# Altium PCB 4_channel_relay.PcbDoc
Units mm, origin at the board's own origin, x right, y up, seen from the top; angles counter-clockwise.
Board outline 102.27 x 70.58 mm, 2 copper layers (Top Layer, Bottom Layer); 40 components, 52 nets, 202 pads, 42 vias.
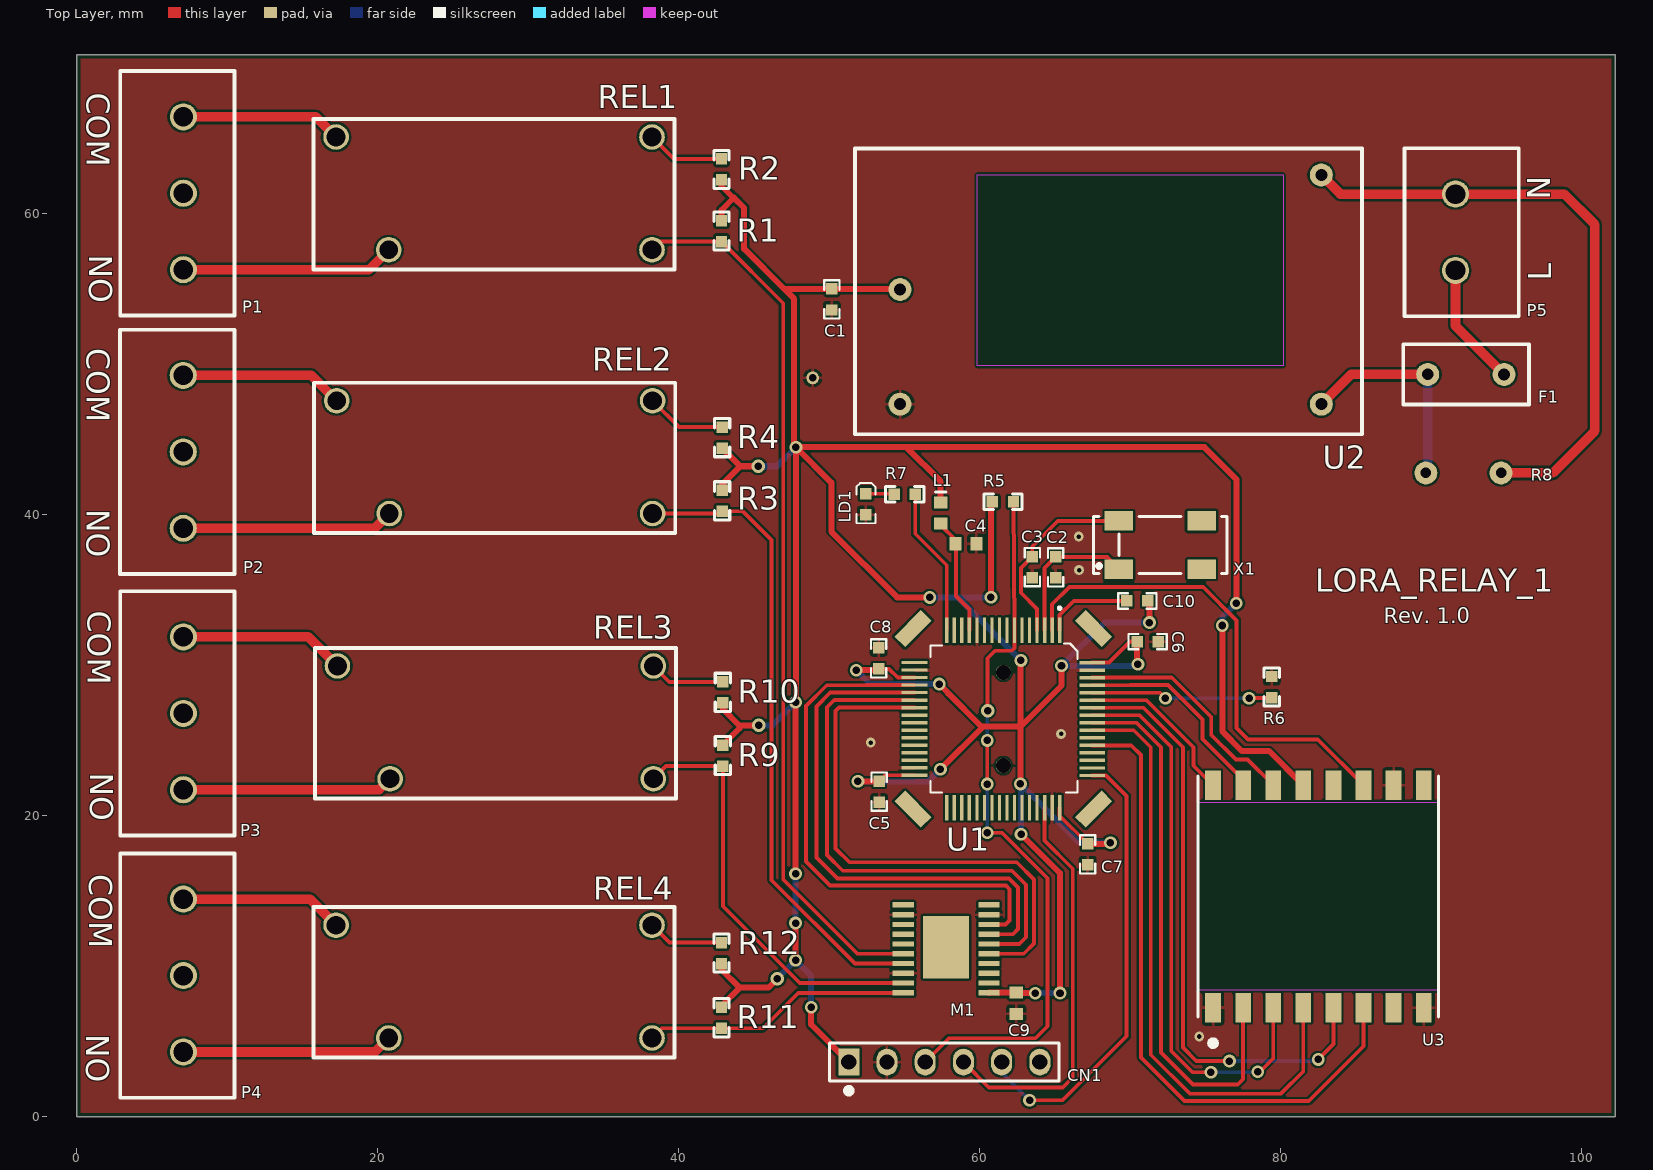
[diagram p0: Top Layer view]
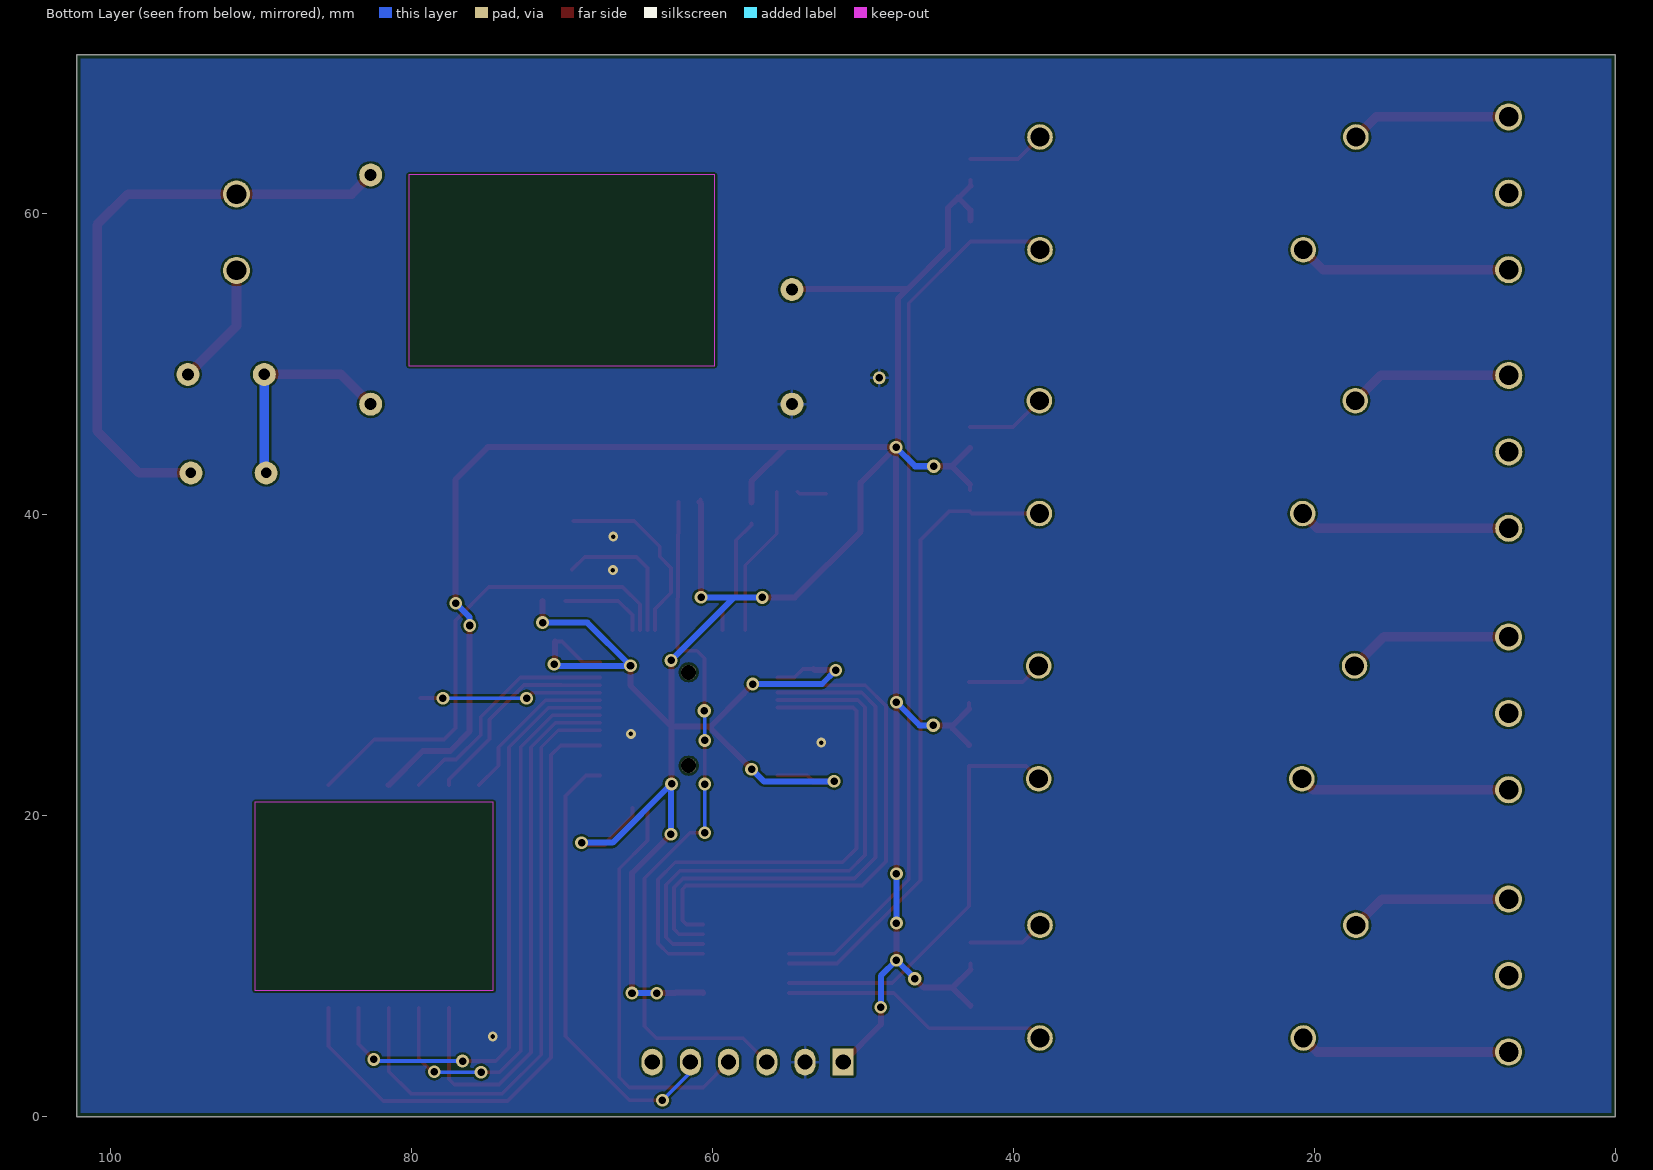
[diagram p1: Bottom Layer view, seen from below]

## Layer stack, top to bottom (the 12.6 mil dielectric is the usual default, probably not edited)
Top Solder: solder mask 0.0102, Solder Resist, Dk 3.5
Top Layer: signal copper 0.0356
Dielectric 1: dielectric 0.32, FR-4, Dk 4.8
Bottom Layer: signal copper 0.0356
Bottom Solder: solder mask 0.0102, Solder Resist, Dk 3.5

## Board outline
0,-0.01 102.27,-0.01 102.27,70.57 0,70.57

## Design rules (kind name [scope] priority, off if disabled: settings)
BoardOutlineClearance [All] p1: gap=0.25 ignorepadtopadclearanceinfootprint=FALSE except(0: Arc-SplitContinuation Track-SplitContinuation SMDPad-SplitContinuation THPad-SplitContinuation Via-SplitContinuation Fill-SplitContinuation Poly-SplitContinuation Region-SplitContinuation Text-SplitContinuation)
Clearance [InNetClass('240VAC')] p1: gap=0.15 ignorepadtopadclearanceinfootprint=FALSE except(0: Arc-Hole Track-Hole SMDPad-Hole THPad-Hole Via-Hole Fill-Hole Poly-Hole Region-Hole Text-Hole; 3: Arc-Arc Arc-Track Track-Track)
Clearance Clearance-xPP-xTP-xTT [All] p2: gap=0.15 ignorepadtopadclearanceinfootprint=FALSE except(0: Arc-Hole Track-Hole SMDPad-Hole THPad-Hole Via-Hole Fill-Hole Poly-Hole Region-Hole Text-Hole)
ComponentClearance [All] p1: gap=0.25 collisioncheckmode=3 verticalgap=0.25 showdistances=FALSE
DiffPairsRouting [All] p1: maxlimit=0.25 minlimit=0.25 mostfreqgap=0.25 toplayer_minwidth=0.381 toplayer_maxwidth=0.381 toplayer_prefwidth=0.381 bottomlayer_minwidth=0.381 bottomlayer_maxwidth=0.381 bottomlayer_prefwidth=0.381 maxuncoupledlength=12.5
Height [All] p1: minheight=0 maxheight=25 prefheight=12.5
HoleSize HoleSize-PTH [All] p1: absolutevalues=TRUE maxlimit=2 minlimit=0.3 maxpercent=80.000 minpercent=20.000
HoleToHoleClearance [All] p1: gap=0.35 allowstackedmicrovias=TRUE
MinimumAnnularRing "Minimum IAR  >0.45mm" [((ObjectKind = 'Pad') OR (ObjectKind = 'Via')) And (Layer = 'MultiLayer') And (HoleDiameter > AsMM(0.45))] p1: minimumring=0.125 // minimum inner annular ring for pads > 0.45mm finished hole size
MinimumAnnularRing "Minimum IAR <=0.45mm" [((ObjectKind = 'Pad') OR (ObjectKind = 'Via')) And (Layer = 'MultiLayer') And (HoleDiameter <= AsMM(0.45))] p2: minimumring=0.175 // minimum inner annular ring for pads <= 0.45mm finished hole size
MinimumSolderMaskSliver [All] p1: minsoldermaskwidth=0.08
PlaneClearance PlaneClearance-IPI [All] p1: clearance=0.25
PlaneConnect [All] p1: planeconnectstyle=Relief reliefexpansion=0.175 reliefentries=4 reliefconductorwidth=0.2 reliefairgap=0.2
PolygonConnect PolygonConnect-xTW [All] p1: connectstyle=Relief reliefconductorwidth=0.2 reliefentries=4 polygonreliefangle="90 Angle" airgapwidth=0.2
RoutingCorners [All] p1: cornerstyle=45-Degree minsetback=2.5 maxsetback=2.5
RoutingVias "RoutingVias > 0.45mm" [(ObjectKind = 'Via') And (HoleDiameter > AsMM(0.45))] p1: holewidth=0.5 width=0.85 viastyle="Through Hole" minholewidth=0.5 minwidth=0.85 maxholewidth=0.9 maxwidth=1.25 // finishet hole size > 0.45mm
RoutingVias "RoutingVias <= 0.45mm" [(ObjectKind = 'Via') And (HoleDiameter <= AsMM(0.45))] p2: holewidth=0.3 width=0.65 viastyle="Through Hole" minholewidth=0.25 minwidth=0.6 maxholewidth=0.45 maxwidth=0.8 // finishet hole size <= 0.45mm
SilkToSilkClearance [All] p1: silktosilkclearance=0.2
SilkToSolderMaskClearance SilkscreenOverComponentPads [IsPad] p1: minsilkscreentomaskgap=0.01 clearancetoexposedcopper=TRUE
SolderMaskExpansion [All] p1: expansion=0
UnRoutedNet [All] p1: checkbadconnections=TRUE
Width Width-xTW [All] p1: maxlimit=1.5 minlimit=0.15 preferedwidth=0.2
18 further rules are at their usual default settings.

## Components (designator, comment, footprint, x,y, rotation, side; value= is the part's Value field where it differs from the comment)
C1 "100nF" 0603C 50.2,54.3 r90 top value=0.1µF
C2 "10pF[N/A]" 0603C 65.07,36.49 r90 top value=10pF
C3 "10pF[N/A]" 0603C 63.52,36.51 r90 top
C4 "Cap Semi" 1608[0603] 59.1,38.07 r0 top
C5 "100nF" 0603C 53.335,21.591 r90 top
C6 "100nF" 0603C 71.19,31.56 r180 top
C7 "100nF" 0603C 67.2,17.42 r90 top
C8 "100nF" 0603C 53.3,30.445 r270 top
C9 "Cap Semi" 1608[0603] 62.45,7.52 r270 top
C10 "100nF" 0603C 70.5,34.26 r0 top value=0.1µF
CN1 "Header 6X1" 1*6P 51.32,3.61 r0 top
F1 "fuse" fuse 94.88,49.32 r180 top value="1A 250VAC"
L1 "Bead" INDC1608L 57.424,40.099 r270 top value="600 OHM"
LD1 "Green" 0603D 52.457,40.695 r90 top value=571nm
M1 "MAX4821" MAX4821 60.64,8.21 r180 top
P1 "relay_header_3" ac_header_3 2.89,53.24 r90 top
P2 "relay_header_3" ac_header_3 2.88,36.05 r90 top
P3 "relay_header_3" ac_header_3 2.89,18.67 r90 top
P4 "relay_header_3" ac_header_3 2.89,1.24 r90 top
P5 "AC_HEADER" ac_header_2 95.85,64.35 r270 top
R1 "50" 0603R 42.86,58.845 r90 top value="50 Ohms"
R2 "50" 0603R 42.86,62.945 r270 top
R3 "50" 0603R 42.9,40.916 r90 top
R4 "50" 0603R 42.9,45.115 r270 top
R5 "4K7" 0603R 61.57,40.85 r0 top value="4.7 kOhms"
R6 "4K7" 0603R 79.44,28.54 r90 top
R7 "510" 0603R 55.04,41.351 r0 top value="510 Ohms"
R8 "" varistor 94.68,42.77 r180 top value="360V 400A"
R9 "50" 0603R 42.95,23.985 r90 top
R10 "50" 0603R 42.95,28.185 r270 top
R11 "50" 0603R 42.86,6.555 r90 top
R12 "50" 0603R 42.86,10.855 r270 top
REL1 "ADW1103W" ADW1103W 39.74,37.7 r180 top
REL2 "ADW1103W" ADW1103W 39.78,20.17 r180 top
REL3 "ADW1103W" ADW1103W 39.83,2.54 r180 top
REL4 "ADW1103W" ADW1103W 39.74,-14.69 r180 top
U1 "MCU_LQFP64" LQFP64 61.59,26.417 r180 top
U2 "RAC01-3.3SC" RAC01-3.3SC 82.73,47.34 r180 top
U3 "RFM95W-868S2" XCVR_RFM95W-868S2 82.534,14.618 r90 top
X1 "32.768K[N/A]" XTAL_4SM_8X3R8 72.02,37.98 r0 top

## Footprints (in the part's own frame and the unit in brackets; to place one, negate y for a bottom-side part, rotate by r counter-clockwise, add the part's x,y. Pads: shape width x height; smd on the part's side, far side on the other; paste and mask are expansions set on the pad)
1*6P [mil]
  rect 55x70 hole 40: 1(0,0)
  oval 55x70 hole 40: 2(400,0) 3(100,0) 4(300,0) 5(200,0) 6(500,0)
  silkscreen extent -50,-82 550,50
0603C [mil]
  rect 30x30 smd: 1(27.5,0) 2(-27.5,0)
  silkscreen extent -50,-20 50,20
0603D [mil]
  rect 30x30 smd: 1(27.5,0) 2(-27.5,0)
  silkscreen extent -50,-25 55,25
0603R [mil]
  rect 30x30 smd: 1(27.5,0) 2(-27.5,0)
  silkscreen extent -50,-20 50,20
1608[0603] [mm] "Chip Capacitor, Body 1.6x0.8mm, IPC High Density"
  rect 0.8x0.9 smd: 1(-0.7,0) 2(0.7,0)
  body extent -0.87,-0.48 0.87,0.48, height 1.3
ac_header_2 [mm] "230VAC 2 pin header"
  round 1.8 hole 1.3: 1(3.04,-4.2) 2(8.12,-4.2)
  silkscreen extent 0,-7.6 11.16,0
ac_header_3 [mm] "230VAC header 3 pin"
  round 1.8 hole 1.3: 1(13.2,-4.2) 2(3.04,-4.2) 3(8.12,-4.2)
  silkscreen extent 0,-7.6 16.24,0
ADW1103W [mm]
  round 1.7 hole 1.25: 1(1.5,-19.9) 2(1.5,-27.4) 3(22.5,-27.4) 4(19,-19.9)
  silkscreen extent 0,-28.6 24,-18.6
fuse [mil] "240VAC 1A"
  round 60 hole 31.5: 1(0,0)
  round 60 hole 30: 2(200,0)
  silkscreen extent -65,-79 264,79
INDC1608L [mm] "Chip Inductor, Body 1.6x0.8mm, IPC High Density"
  rect 0.8x0.9 smd: 1(-0.7,0) 2(0.7,0)
  silkscreen extent -1.4,-0.35 -1.4,0.35, body extent -0.87,-0.48 0.87,0.48, height 0.55
LQFP64 [mm]
  rect 1x2.5 smd rot 135: 0(-6,6) 0(6,-6)
  rect 1x2.5 smd rot 45: 0(-6,-6) 0(6,6)
  round 1 hole 1 unplated: 0(0,3.1) 0(0,-3.1)
  rect 0.22x1.7 smd: 1(-3.747,-5.901) 2(-3.247,-5.901) 3(-2.747,-5.901) 4(-2.247,-5.901) 5(-1.747,-5.901) 6(-1.247,-5.901) 7(-0.747,-5.901) 8(-0.247,-5.901) 9(0.253,-5.901) 10(0.753,-5.901) 11(1.253,-5.901) 12(1.753,-5.901) 13(2.253,-5.901) 14(2.753,-5.901) 15(3.253,-5.901) 16(3.753,-5.901) 33(3.753,5.902) 34(3.253,5.902) 35(2.753,5.902) 36(2.253,5.902) 37(1.753,5.902) 38(1.253,5.902) 39(0.753,5.902) 40(0.253,5.902) 41(-0.247,5.902) 42(-0.747,5.902) 43(-1.247,5.902) 44(-1.747,5.902) 45(-2.247,5.902) 46(-2.747,5.902) 47(-3.247,5.902) 48(-3.747,5.901)
  rect 1.7x0.22 smd: 17(5.901,-3.753) 18(5.901,-3.253) 19(5.901,-2.753) 20(5.901,-2.253) 21(5.901,-1.753) 22(5.901,-1.253) 23(5.901,-0.753) 24(5.901,-0.253) 25(5.901,0.247) 26(5.901,0.747) 27(5.901,1.247) 28(5.901,1.747) 29(5.901,2.247) 30(5.901,2.747) 31(5.901,3.247) 32(5.901,3.747) 49(-5.902,3.753) 50(-5.902,3.253) 51(-5.902,2.753) 52(-5.902,2.253) 53(-5.902,1.753) 54(-5.902,1.253) 55(-5.902,0.753) 56(-5.902,0.253) 57(-5.902,-0.247) 58(-5.902,-0.747) 59(-5.902,-1.247) 60(-5.902,-1.747) 61(-5.902,-2.247) 62(-5.902,-2.746) 63(-5.902,-3.246) 64(-5.902,-3.746)
  silkscreen extent -4.94,-7.42 4.84,4.89
MAX4821 [mm]
  rect 1.4x0.35 smd: 1(0,0) 2(0,-0.65) 3(0,-1.3) 4(0,-1.95) 5(0,-2.6) 6(0,-3.25) 7(0,-3.9) 8(0,-4.55) 9(0,-5.2) 10(0,-5.85) 11(5.7,-5.85) 12(5.7,-5.2) 13(5.7,-4.55) 14(5.7,-3.9) 15(5.7,-3.25) 16(5.7,-2.6) 17(5.7,-1.95) 18(5.7,-1.3) 19(5.7,-0.65) 20(5.7,0)
  rect 3.05x4.13 smd: 30(2.86,-3.03)
RAC01-3.3SC [mil] "AC/DC converter"
  round 60 hole 31.5: 1(0,0) 2(0,-600) 3(1102.36,0) 4(1102.36,-300)
  Keep-Out Layer region: 100,-100 900,-100 900,-600 100,-600
  silkscreen extent -106,-669 1220,79
varistor [mil]
  round 60 hole 27.56: 1(0,0) 2(196.85,0)
XCVR_RFM95W-868S2 [mm]
  rect 1.95x1.05 smd: 1(-7.4,7) 2(-7.4,5) 3(-7.4,3) 4(-7.4,1) 5(-7.4,-1) 6(-7.4,-3) 7(-7.4,-5) 8(-7.4,-7) 9(7.4,-7) 10(7.4,-5) 11(7.4,-3) 12(7.4,-1) 13(7.4,1) 14(7.4,3) 15(7.4,5) 16(7.4,7)
  silkscreen extent -10.04,-8 8,8
XTAL_4SM_8X3R8 [mm]
  rect 1.9x1.3 smd: 1(-2.75,-1.6) 2(2.75,-1.6) 3(2.75,1.6) 4(-2.75,1.6)
  silkscreen extent -4.44,-1.91 4.44,1.91

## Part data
C1 C10: library part Cap, "Capacitor", Manufacturer="AVX Corporation"
C2: library part Cap, "Capacitor", Manufacturer="Murata Electronics North America"
C3: library part CAP, "Capacitor", Manufacturer="Murata Electronics North America"
C4 C9: "Capacitor (Semiconductor SIM Model)", Manufacturer=TDK
C5 C6 C7 C8: library part Cap, "Capacitor", Manufacturer=TDK
CN1: "Header, 6-Pin, Single row", Manufacturer=Molex
F1: "240VAC 1A", Manufacturer="Bel Fuse Inc."
L1: library part Inductor, "Inductor", Manufacturer="Taiyo Yuden"
LD1: library part LED2, "Typical RED, GREEN, YELLOW, AMBER GaAs LED", Manufacturer=Lite-On
M1: Manufacturer="Maxim Integrated"
P1 P2 P3 P4 P5: Manufacturer="On Shore Technology"
R1 R2 R3 R4 R9 R10 R11 R12: library part Res1, "Resistor", Manufacturer="Vishay Dale"
R5 R6: library part Res1, "Resistor", Manufacturer=Yageo
R7: library part Res1, "Resistor", Manufacturer="Rohm Semiconductor"
R8: library part Res1, "Resistor", Manufacturer="Epcos (TDK)"
REL1 REL2 REL3 REL4: Manufacturer=Panasonic
U1: Manufacturer=STM
U2: "AC/DC converter", Manufacturer="Recom Power"
U3: Manufacturer="RF Solutions", Package="SMD-16 Hope Microelectronics"
X1: library part MC306

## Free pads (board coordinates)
  round 0.85 hole 0.5: 24(48.92,49.09)

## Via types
v1: diameter 0.85, hole 0.5, Top Layer to Bottom Layer, 33 vias
v2: diameter 0.65, hole 0.3, Top Layer to Bottom Layer, 5 vias
v3: diameter 0.9, hole 0.5, Top Layer to Bottom Layer, 4 vias

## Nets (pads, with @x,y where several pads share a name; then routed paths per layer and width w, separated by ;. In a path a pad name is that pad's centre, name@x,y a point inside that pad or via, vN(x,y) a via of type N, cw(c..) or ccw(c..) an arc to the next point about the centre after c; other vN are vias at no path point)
GND: C1.2 C2.2 C3.2 C4.2 C5.2 C6.2 C7.2 C8.2 C9.2 CN1.3 LD1.2 M1.9 M1.12 M1.18 pad.24 R6.1 U1.12 U1.18 U1.31 U1.47 U1.63 U2.3 U3.1 U3.8 U3.10
  other v2: 74.62,5.31 52.78,24.85 65.43,25.42 66.63,36.31 66.61,38.54
NetC2_1: C2.1 U1.3 X1.1 | length 9.8
  Top Layer w0.254: U1.3 64.337,36.455 C2.1 68.502,37.189 X1.1@69.34,36.35
NetC3_1: C3.1 U1.4 X1.4 | length 12.8
  Top Layer w0.254: U1.4 63.837,33.733 62.76,34.81 62.76,36.448 C3.1 63.52,37.89 65.21,39.58 X1.4
NetC4_1: C4.1 L1.2 U1.13 | length 7.9
  Top Layer w0.254: L1.2 57.421,39.396 57.421,39.319 58.44,38.3 58.44,34.59 59.337,33.693 U1.13
NetC10_2: C10.2 U1.1 | length 5.9
  Top Layer w0.254: U1.1 65.337,33.327 66.27,34.26 C10.2
NetF1_1: F1.1 P5.2 | length 8.2
  Top Layer w0.635: P5.2 91.65,52.55 F1.1
NetF1_2: F1.2 R8.2 U2.1 | length 14.5
  Top Layer w0.635: U2.1 84.71,49.32 F1.2
  Bottom Layer w0.635: R8.2 89.8,42.89 F1.2
NetLD1_1: LD1.1 R7.2 | length 2
  Top Layer w0.254: LD1.1 54.235,41.393 R7.2@54.362,41.52
NetM1_5: M1.5 U1.23 | length 36.1
  Top Layer w0.254: U1.23 50.66,27.17 50.436,26.946 50.436,17.814 51.36,16.89 62.49,16.89 63.63,15.75 63.63,11.49 62.95,10.81 M1.5
NetM1_6: M1.6 U1.22 | length 36
  Top Layer w0.254: U1.22 50.35,27.67 49.876,27.196 49.876,17.374 50.92,16.33 62.17,16.33 63.1,15.4 63.1,11.91 62.65,11.46 M1.6
NetM1_7: M1.7 U1.21 | length 36
  Top Layer w0.254: U1.21 50.09,28.17 49.166,27.246 49.166,17.204 50.56,15.81 61.97,15.81 62.576,15.204 62.576,12.446 62.24,12.11 M1.7
NetM1_8: M1.8 U1.20 | length 35.9
  Top Layer w0.254: U1.20 52.5,28.67 52.49,28.66 49.86,28.66 48.486,27.286 48.486,16.934 50.08,15.34 61.76,15.34 62,15.1 62,13.02 61.74,12.76 M1.8
NetP1_1: P1.1 REL1.3 | length 10.7
  Top Layer w0.635: P1.1 15.9,66.44 REL1.3
NetP1_2: P1.2 REL1.4 | length 14.2
  Top Layer w0.635: P1.2 19.42,56.28 REL1.4
NetP2_1: P2.1 REL2.3 | length 10.9
  Top Layer w0.635: P2.1 15.6,49.25 REL2.3
NetP2_2: P2.2 REL2.4 | length 14.1
  Top Layer w0.635: P2.2 19.8,39.09 REL2.4
NetP3_1: P3.1 REL3.3 | length 11
  Top Layer w0.635: P3.1 15.4,31.87 REL3.3
NetP3_2: P3.2 REL3.4 | length 14
  Top Layer w0.635: P3.2 20.1,21.71 REL3.4
NetP4_1: P4.1 REL4.3 | length 10.9
  Top Layer w0.635: P4.1 15.51,14.44 REL4.3
NetP4_2: P4.2 REL4.4 | length 14
  Top Layer w0.635: P4.2 19.81,4.28 REL4.4
NetP5_1: P5.1 R8.1 U2.2 | length 40.7
  Top Layer w0.635: U2.2 84,61.31 P5.1 98.88,61.31 100.91,59.28 100.91,45.56 98.12,42.77 R8.1
NetR2_2: R2.2 REL1.2 | length 5.2
  Top Layer w0.254: REL1.2 39.696,63.643 R2.2
NetR4_2: R4.2 REL2.2 | length 5.3
  Top Layer w0.254: REL2.2 40.036,45.813 R4.2
NetR6_2: R6.2 U1.60 | length 12.1
  Top Layer w0.254: U1.60 71.996,28.164 v1(72.37,27.79) ; v1(77.93,27.8) 77.94,27.81 R6.2@79.44,27.81
  Bottom Layer w0.254: v1(72.37,27.79) 77.92,27.79 v1(77.93,27.8)
NetR10_2: R10.2 REL3.2 | length 5.1
  Top Layer w0.254: REL3.2 39.386,28.884 R10.2
NetR12_2: R12.2 REL4.2 | length 5.1
  Top Layer w0.254: REL4.2 39.396,11.553 R12.2
NRST: CN1.5 R5.1 U1.7 | length 47.8
  Top Layer w0.254: CN1.5 57.98,5.19 63.72,5.19 64.52,5.99 64.52,15.83 61.5,18.85 v1(60.52,18.85) ; v1(60.52,22.09) v1(60.52,24.99) v1@60.52,25.2 ; v3(60.55,26.97) 60.55,30.451 61.05,30.951 62.15,30.951 62.337,31.138 U1.7 R5.1
  Bottom Layer w0.254: v1(60.52,18.85) v1(60.52,22.09) ; v1(60.52,24.99) 60.52,26.94 v3(60.55,26.97)
OUT1: M1.20 R11.2 REL4.1 | length 17.9
  Top Layer w0.254: REL4.1 38.886,5.856 R11.2 45.606,5.856 47.96,8.21 M1.20
OUT2: M1.19 R9.2 REL3.1 | length 28.4
  Top Layer w0.254: REL3.1 39.176,23.286 R9.2 42.95,13.97 48.06,8.86 M1.19
OUT3: M1.17 R3.2 REL2.1 | length 43
  Top Layer w0.254: REL2.1@38.658,40.448 REL2.1 42.752,40.07 R3.2 44.282,40.218 46.19,38.31 46.19,15.7 51.73,10.16 M1.17
OUT4: M1.16 R1.2 REL1.1 | length 59
  Top Layer w0.254: REL1.1 38.787,58.147 R1.2 46.96,54.046 46.96,15.75 51.9,10.81 M1.16
PA2: R7.1 U1.16 | length 10.1
  Top Layer w0.254: R7.1@55.738,41.51 R7.1 55.738,38.732 57.837,36.633 U1.16
PA3: U1.17
PA8: U1.41
PA9: U1.42
PA10: U1.43
PB3: U1.55 U3.4 | length 40.9
  Top Layer w0.254: U1.55 70.266,25.664 71.39,24.54 71.39,4.1 73.98,1.51 80.06,1.51 81.534,2.984 U3.4
PB4: U1.56 U3.2 | length 36.8
  Top Layer w0.254: U1.56 70.456,26.164 72.08,24.54 72.08,4.24 74.21,2.11 77.18,2.11 77.534,2.464 U3.2
PB5: U1.57 U3.3 | length 37.5
  Top Layer w0.254: U1.57 70.636,26.664 72.76,24.54 72.76,4.33 74.16,2.93 v1(75.39,2.93) ; v1(78.5,2.97) 78.65,2.97 79.534,3.854 U3.3
  Bottom Layer w0.254: v1(75.39,2.93) 78.46,2.93 v1(78.5,2.97)
PB6: U1.58 U3.5 | length 40.5
  Top Layer w0.254: U1.58 70.906,27.164 73.53,24.54 73.53,4.57 74.42,3.68 v1(76.62,3.68) ; v1(82.52,3.79) 83.534,4.804 U3.5
  Bottom Layer w0.254: v1@76.62,3.69 v1@82.52,3.69 ; v1(82.52,3.79) v1@82.52,4.01
PB7: U1.59 U3.16 | length 11.1
  Top Layer w0.254: U1.59 71.116,27.664 74.24,24.54 74.24,23.312 U3.16
PB8: U1.61 U3.15 | length 13.8
  Top Layer w0.254: U1.61 70.03,28.685 72.545,28.685 74.84,26.39 74.84,25.08 77.534,22.386 U3.15
PB9: U1.62 U3.14 | length 15.7
  Top Layer w0.254: U1.62 72.786,29.164 75.41,26.54 75.41,25.36 77.05,23.72 77.832,23.72 U3.14
PB11: U1.30
PC6: U1.37
PC9: U1.40
PC12: U1.53 U3.6 | length 43.7
  Top Layer w0.254: U1.53 70.096,24.664 70.74,24.02 70.74,3.92 73.64,1.02 81.89,1.02 85.534,4.664 U3.6
PC13: U1.2 U3.11 | length 32.5
  Top Layer w0.254: U1.2 64.837,34.038 65.989,35.19 74.88,35.19 77.1,32.97 77.1,25.81 77.85,25.06 82.492,25.06 U3.11
SWO: CN1.6
TCK: CN1.2 U1.49 | length 30.4
  Top Layer w0.254: v1(63.34,1.07) 65.53,1.07 69.79,5.33 69.79,21.29 68.416,22.664 U1.49
  Bottom Layer w0.254: CN1.2 61.48,2.93 v1(63.34,1.07)
TMS: CN1.4 U1.46 | length 26.9
  Top Layer w0.254: CN1.4 60.62,1.93 65.54,1.93 66.21,2.6 66.21,16.46 64.337,18.333 U1.46
VDD: C1.1 C5.1 C6.1 C7.1 C8.1 C9.1 C10.1 CN1.1 L1.1 M1.1 R1.1 R2.1 R3.1 R4.1 R5.2 R9.1 R10.1 R11.1 R12.1 U1.19 U1.32 U1.48 U1.64 U2.4 U3.13 | length 281.3
  Top Layer w0.254: R11.1 R11.1@42.86,7.355 ; 42.86,9.755 R12.1 ; 42.86,61.845 R2.1 ; R3.1 42.9,42.013 ; 42.95,27.085 R10.1 ; 44.05,25.783 44.05,25.985 ; C8.1 53.999,29.747 54.575,29.17 U1.19 ; C5.1 53.716,22.671 U1.32 ; R5.2@60.812,40.79 R5.2@60.812,41.02 ; U1.48 65.337,19.982 C7.1 ; U1.64 68.624,30.164 70.02,31.56 C6.1
  Top Layer w0.4: R11.1@42.86,7.355 44.06,8.555 ; 42.86,9.755 44.06,8.555 ; R1.1 42.86,60.245 43.66,61.045 ; 42.86,61.845 43.66,61.045 ; 42.9,42.013 44.101,43.215 ; R4.1 44.101,43.215 ; R9.1 44.05,25.783 ; 42.95,27.085 44.05,25.985 v3(45.35,25.985) ; v3(45.3,43.215) 44.101,43.215 ; v3(46.57,9.14) 45.985,8.555 44.06,8.555 ; v1(47.78,10.38) v1(47.78,12.85) ; v1(47.78,16.13) v1(47.78,27.53) 47.81,27.56 v1(47.81,44.48) ; v1(48.82,7.26) 48.82,6.11 CN1.1 ; v1(51.81,29.66) 53.214,29.66 C8.1 ; v1(51.93,22.27) 53.316,22.27 C5.1 ; U2.4 54.692,54.999 C1.1 47.031,54.999 ; v1(56.7,34.5) 54.53,34.5 50.16,38.87 50.16,42.13 v1(47.81,44.48) ; v1(57.33,28.74) 57.925,28.145 57.925,28.125 60.141,25.909 60.239,25.909 ; v1(57.41,23.08) 60.239,25.909 ; L1.1 57.424,42.206 55.15,44.48 ; M1.1 60.65,8.22 C9.1 62.48,8.19 v1(63.72,8.19) ; v1(60.77,34.51) 60.77,40.749 60.812,40.79 R5.2 ; v1(62.733,22.103) 62.733,25.909 ; v1(62.76,30.31) 62.733,30.283 62.733,25.909 ; v1(62.77,18.76) 65.36,16.17 v1(65.36,8.2) ; v1(65.46,29.95) 65.46,28.636 62.733,25.909 ; C7.1 68.639,18.119 v1(68.71,18.19) ; C6.1 70.491,30.109 v1(70.54,30.06) ; v1(71.302,32.82) C10.1@71.302,34.26 ; v1(76.15,32.63) 76.15,25.59 77.45,24.29 79.262,24.29 U3.13 ; v1(77.08,34.11) 77.08,42.35 74.95,44.48 55.15,44.48 ; 43.66,61.045 43.677,61.062 44.36,60.38 44.36,57.67 47.031,54.999 ; 47.031,54.999 47.69,54.34 47.69,44.6 v1(47.81,44.48) ; v1(47.81,44.48) 55.15,44.48 ; 60.239,25.909 62.733,25.909
  Bottom Layer w0.4: v3(45.3,43.215) 46.545,43.215 v1(47.81,44.48) ; v3(45.35,25.985) 46.235,25.985 v1(47.78,27.53) ; v3(46.57,9.14) 46.57,9.17 v1(47.78,10.38) 48.82,9.34 v1(48.82,7.26) ; v1(47.78,12.85) v1(47.78,16.13) ; v1(51.81,29.66) 52.73,28.74 v1(57.33,28.74) ; v1(51.93,22.27) 56.6,22.27 v1(57.41,23.08) ; v1(56.7,34.5) 58.57,34.5 ; v1(60.77,34.51) 60.76,34.5 58.57,34.5 ; v1(62.733,22.103) v1@62.77,22.066 ; v1(62.76,30.31) 58.57,34.5 ; v1(62.77,18.76) v1@62.77,22.066 ; v1(63.72,8.19) 65.35,8.19 v1(65.36,8.2) ; v1(68.71,18.19) 66.646,18.19 v1@62.77,22.066 ; v1(70.54,30.06) 70.54,29.84 70.43,29.95 v1(65.46,29.95) 68.33,32.82 v1(71.302,32.82) ; v1(76.15,32.63) 76.15,33.18 v1(77.08,34.11)
pads on no net: M1.2 M1.3 M1.4 M1.10 M1.11 M1.13 M1.14 M1.15 M1.30 P1.3 P2.3 P3.3 P4.3 U1.0 U1.5 U1.6 U1.8 U1.9 U1.10 U1.11 U1.14 U1.15 U1.24 U1.25 U1.26 U1.27 U1.28 U1.29 U1.33 U1.34 U1.35 U1.36 U1.38 U1.39 U1.44 U1.45 U1.50 U1.51 U1.52 U1.54 U3.7 U3.9 U3.12 X1.2 X1.3

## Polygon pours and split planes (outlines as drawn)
GND on Bottom Layer "Top Layer-No Net" (solid, pour order 6): 0.06,70.47 101.97,70.47 102.12,70.62 102.34,70.4 102.34,0.05 0.07,0.05 -0.01,-0.03
GND on Top Layer "Top Layer-No Net" (solid, pour order 4): 0,70.54 0.03,70.57 102.26,70.57 102.26,-0.01 0.01,-0.01

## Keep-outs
Keep-Out Layer:
  region: 74.58,20.875 90.43,20.875 90.43,8.375 74.58,8.375

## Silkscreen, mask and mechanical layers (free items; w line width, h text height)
Top Overlay:
  text "COM" at 0.68,68.03 h1.52 r270
  text "N" at 97.96,60.94 h1.52 r90
  text "NO" at 0.84,57.26 h1.52 r270
  text "L" at 98.01,55.55 h1.52 r90
  text "COM" at 0.68,51.06 h1.52 r270
  text "NO" at 0.68,40.37 h1.52 r270
  text "LORA_RELAY_1" at 82.34,34.86 h1.52
  text "COM" at 0.73,33.62 h1.52 r270
  text "Rev. 1.0" at 86.89,32.78 h1.02
  text "NO" at 0.89,22.83 h1.52 r270
  text "COM" at 0.84,16.09 h1.52 r270
  text "NO" at 0.63,5.46 h1.52 r270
